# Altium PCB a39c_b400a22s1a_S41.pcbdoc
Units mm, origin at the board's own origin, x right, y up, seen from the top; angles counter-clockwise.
Board outline 54.4 x 43.1 mm, 2 copper layers (Top Layer, Bottom Layer); 0 components, 0 nets, 6 pads, 0 vias.
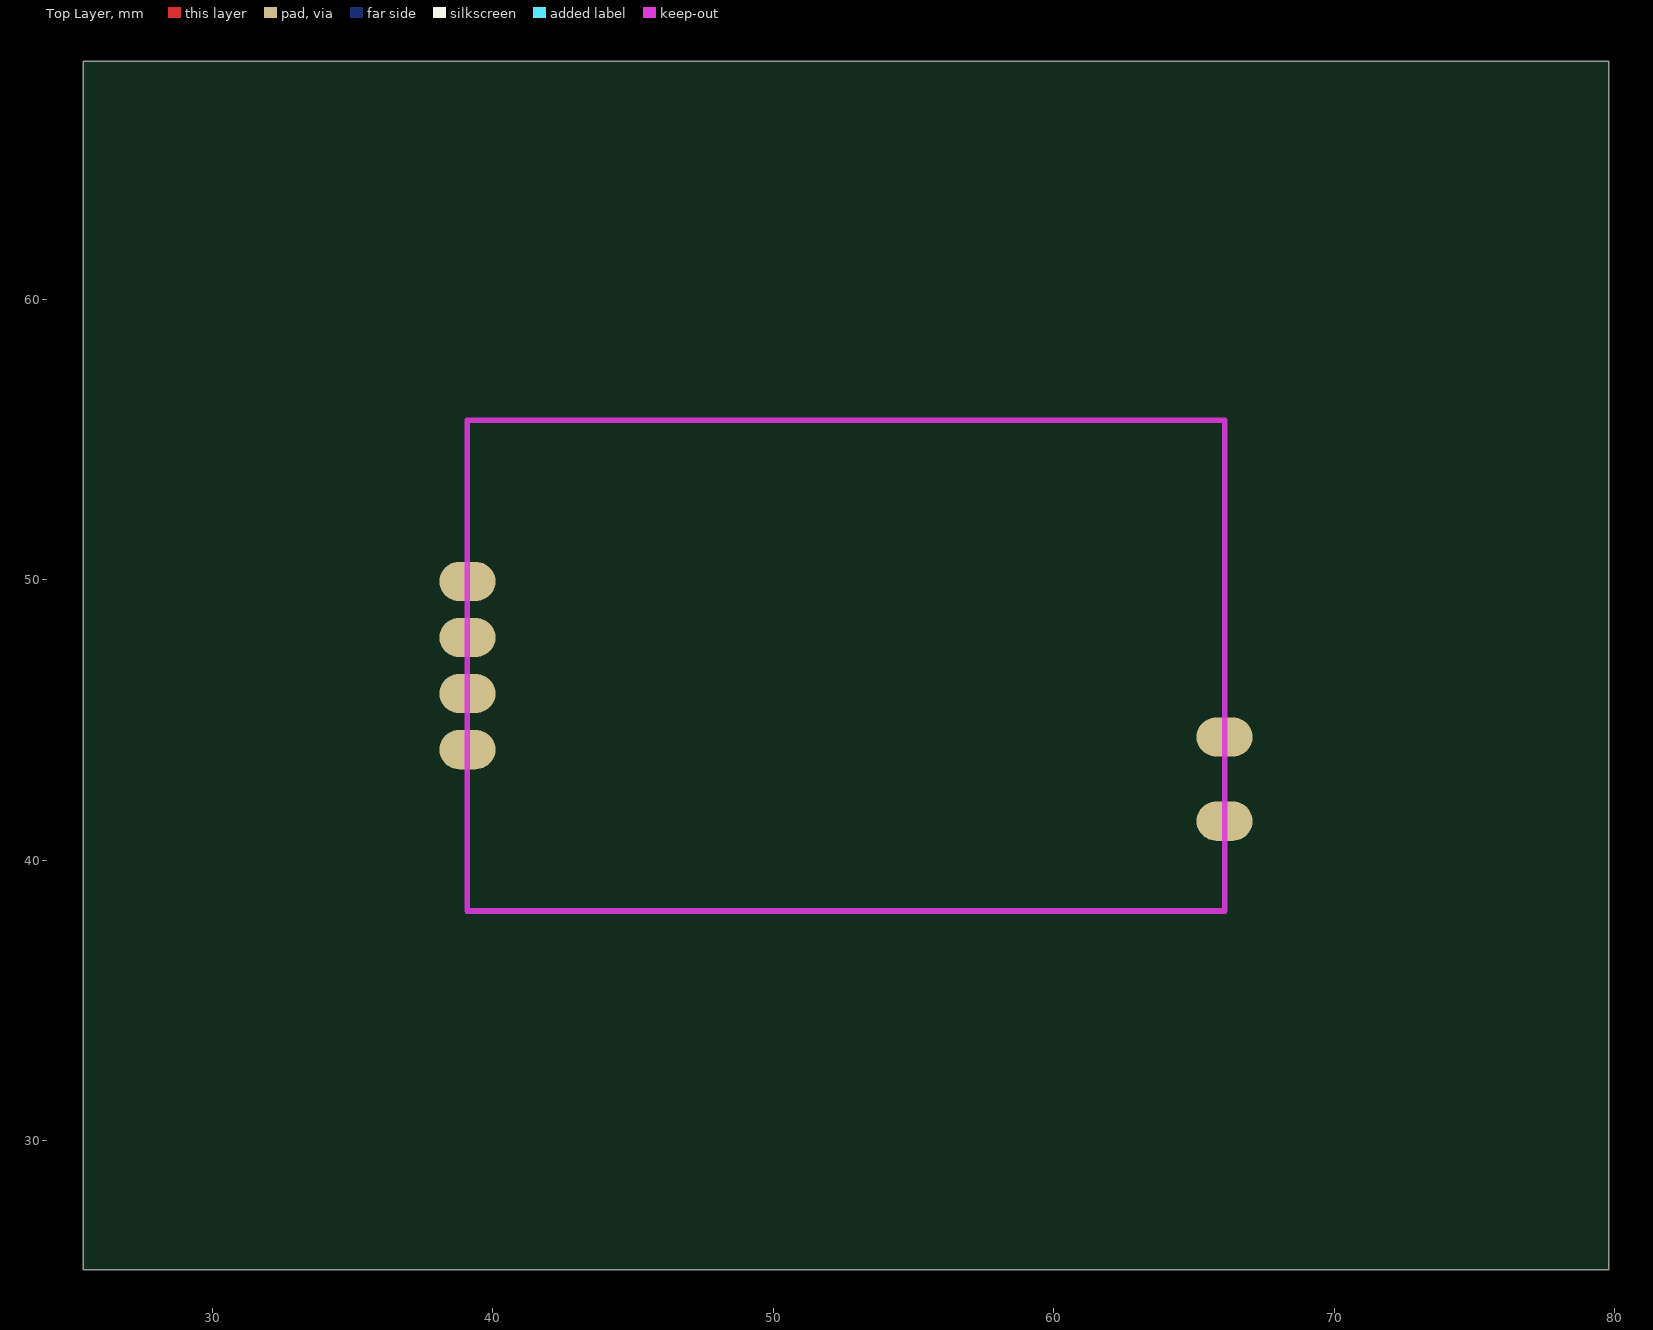
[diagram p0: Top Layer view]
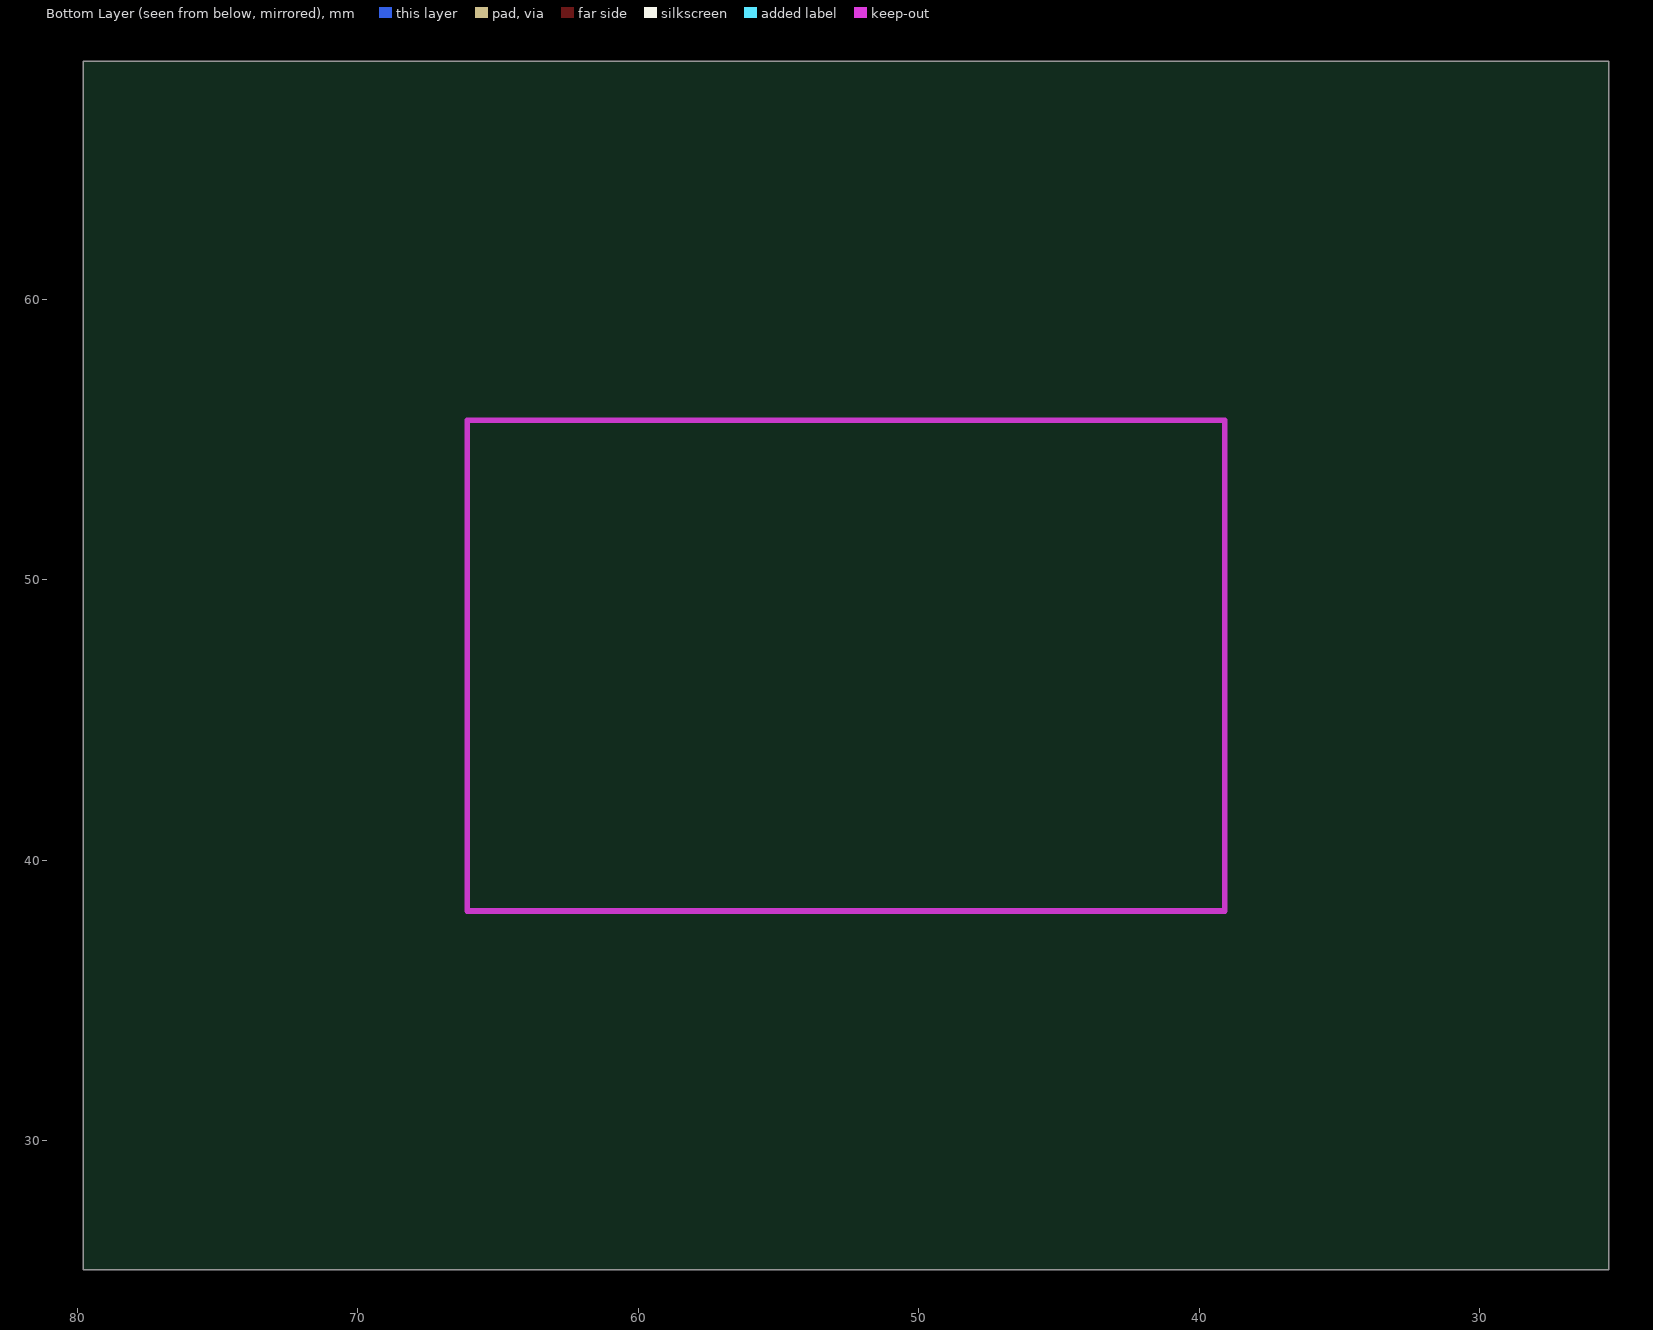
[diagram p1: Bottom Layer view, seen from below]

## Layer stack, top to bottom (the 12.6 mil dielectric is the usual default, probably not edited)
Top Layer: signal copper (thickness not stored)
Dielectric: dielectric 0.32, FR-4, Dk 4.8
Bottom Layer: signal copper (thickness not stored)

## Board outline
79.8,25.4 25.4,25.4 25.4,68.5 79.8,68.5

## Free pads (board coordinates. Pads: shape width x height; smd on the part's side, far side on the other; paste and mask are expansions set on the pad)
  oval 2x1.4 smd: 1(39.1,49.95) 2(39.1,47.95) 3(39.1,45.95) 4(39.1,43.95) 15(66.1,41.4) 16(66.1,44.4)

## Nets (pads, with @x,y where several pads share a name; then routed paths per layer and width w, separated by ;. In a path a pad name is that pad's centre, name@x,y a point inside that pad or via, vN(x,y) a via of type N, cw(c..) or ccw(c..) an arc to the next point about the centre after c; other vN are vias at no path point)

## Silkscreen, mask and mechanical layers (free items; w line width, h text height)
Document:
  lines w0.003: 52.575,46.925 52.625,46.975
